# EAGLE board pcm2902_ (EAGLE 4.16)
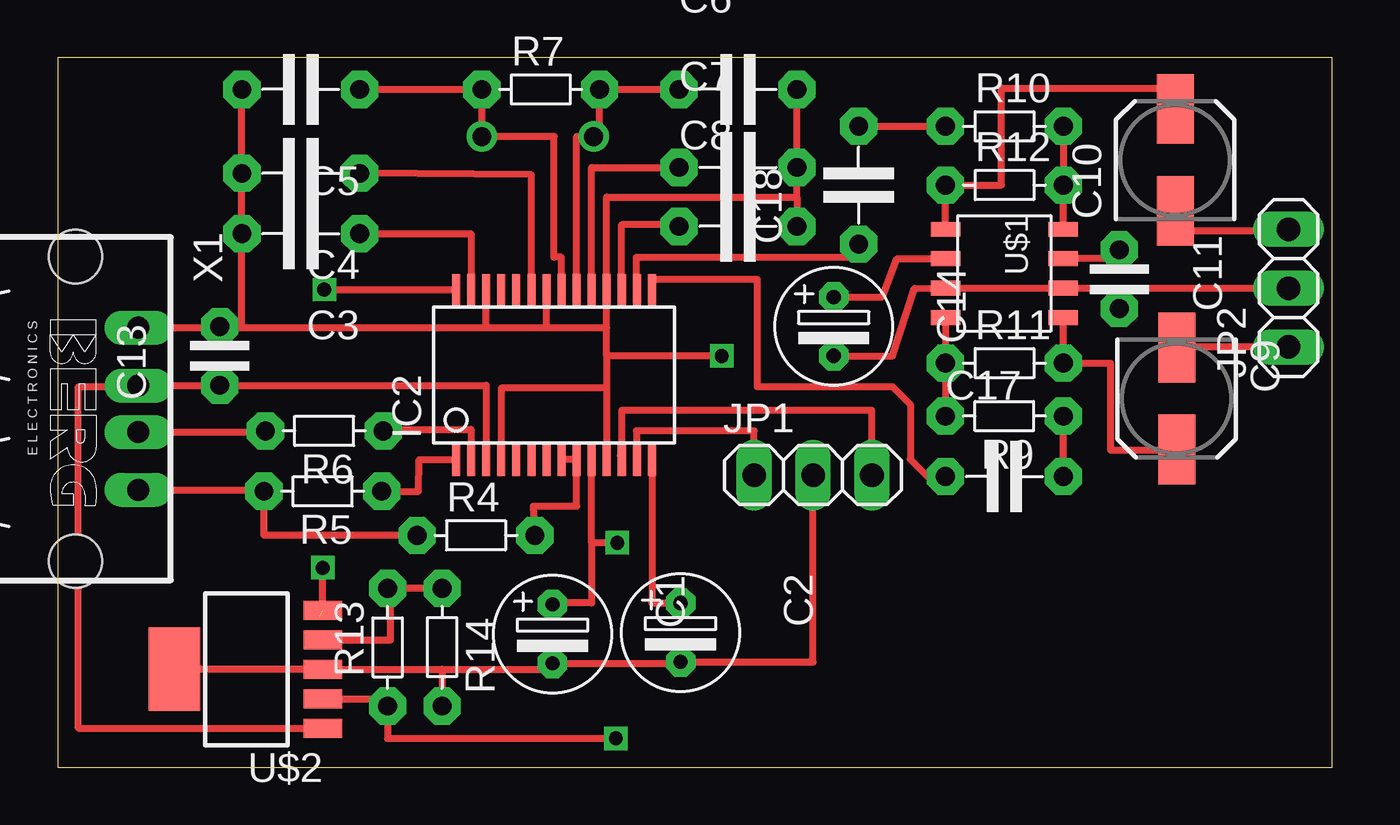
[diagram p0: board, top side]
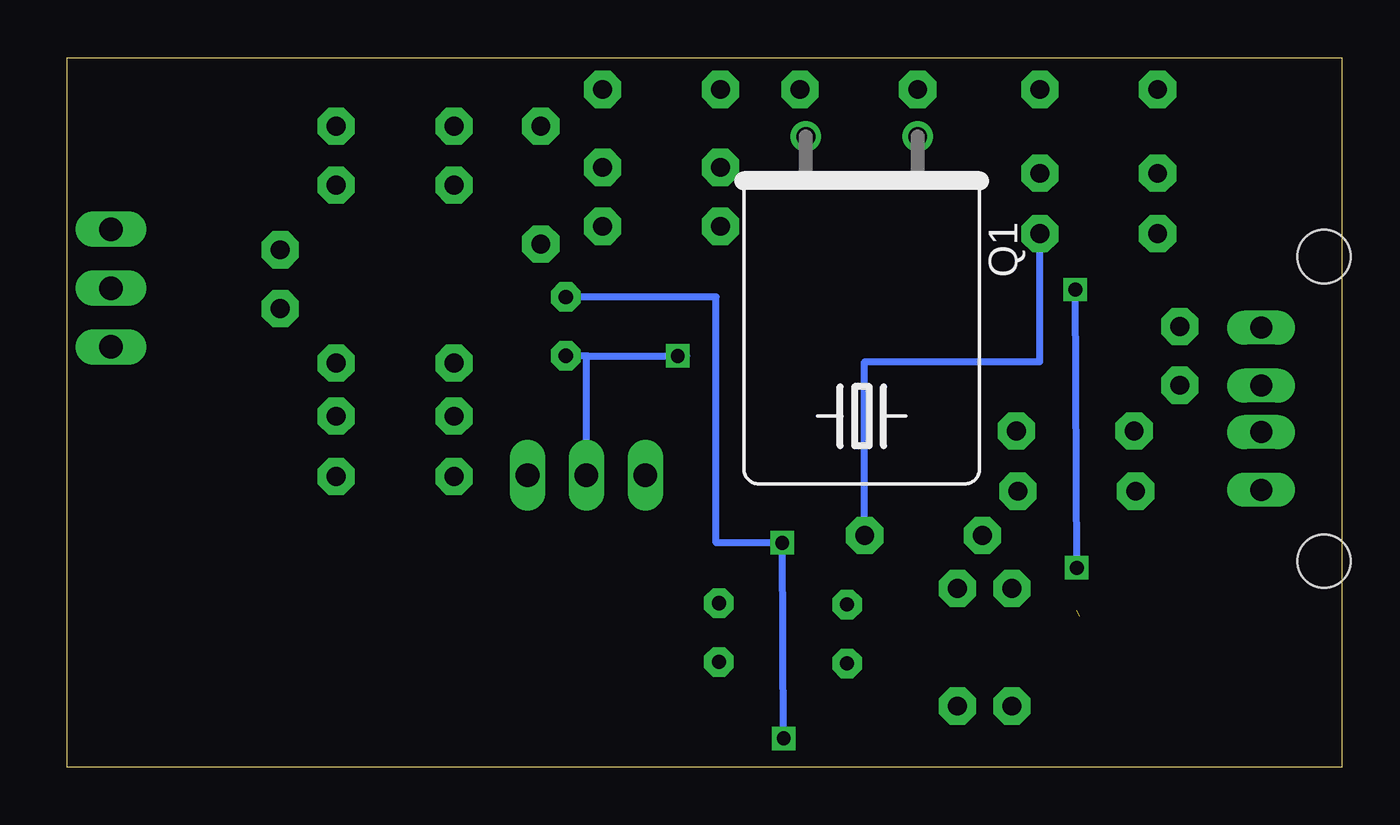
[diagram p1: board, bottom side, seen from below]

Size 54.97 x 30.59 mm. Coordinates in mm from the lower left corner, seen from the top.
Outline: 0,0 54.97,0 54.97,30.59 0,30.59 0,0
Copper layers (1*16): Top 0.035mm / dielectric 1.5mm / Bottom 0.035mm
Design rules "default": minimum track width 10mil, minimum drill 24mil, track to track 8mil, track to pad 8mil, pad to pad 8mil, via to via 8mil, smd to smd 8mil, copper to edge 40mil, drill to drill 8mil, minimum pad ring 10mil, minimum via ring 8mil, stop-mask expansion 4mil, vias tented up to drill 0mil, thermal gap 10mil

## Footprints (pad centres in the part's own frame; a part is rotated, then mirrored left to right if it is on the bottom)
ES-2,5L = drill 0.61 pad 1.27 octagon: 1 0,0; 2 2.54,0
C-5 = drill 0.813 pad 1.6 octagon: 1 -2.54,0; 2 2.54,0
SANYO-OSCON_SMD_B6 = smd 3 x 1.6: + 2.2,0; - -2.2,0
C-2,5 = drill 0.813 pad 1.6 octagon: 1 -1.27,0; 2 1.27,0
SSOP28DB = smd 0.348 x 1.397: 1 -4.225,-3.656; 2 -3.575,-3.656; 3 -2.925,-3.656; 4 -2.275,-3.656; 5 -1.625,-3.656; 6 -0.975,-3.656; 7 -0.325,-3.656; 8 0.325,-3.656; 9 0.975,-3.656; 10 1.625,-3.656; 11 2.275,-3.656; 12 2.925,-3.656; 13 3.575,-3.656; 14 4.225,-3.656; 15 4.225,3.656; 16 3.575,3.656; 17 2.925,3.656; 18 2.275,3.656; 19 1.625,3.656; 20 0.975,3.656; 21 0.325,3.656; 22 -0.325,3.656; 23 -0.975,3.656; 24 -1.625,3.656; 25 -2.275,3.656; 26 -2.925,3.656; 27 -3.575,3.656; 28 -4.225,3.656
1X03 = drill 1.016 long: 1 -2.54,0; 2 0,0; 3 2.54,0
HC49U-H = drill 0.813 round: 1 -2.413,-5.08; 2 2.413,-5.08
R-5 = drill 0.813 pad 1.6 octagon: 1 -2.54,0; 2 2.54,0
SOP8 = smd 0.635 x 1.27: 1 -1.905,-2.54; 2 -0.635,-2.54; 3 0.635,-2.54; 4 1.905,-2.54; 5 1.905,2.54; 6 0.635,2.54; 7 -0.635,2.54; 8 -1.905,2.54
SOT223-5 = smd 0.813 x 1.676: ADJ 1.27,-3.302; EN 2.54,-3.302; GND 0,-3.302; VIN -2.54,-3.302; VOUT -1.27,-3.302 | smd 3.6 x 2.2: TAB 0,3.099
PN87520 = drill 0.95 long: 1 -3.5,2.71; 2 -1,2.71; 3 1,2.71; 4 3.5,2.71 | hole 2.3: -6.57,0; 6.57,0

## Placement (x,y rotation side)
C1  10uF  [ES-2,5L]  21.33,7.01 270 top
C2  10uF  [ES-2,5L]  26.86,7.07 270 top
C3  1uF  [C-5]  10.47,23.01 180 top
C4  1uF  [C-5]  10.47,25.62 180 top
C5  33pF  [C-5]  10.47,29.24 180 top
C6  33pF  [C-5]  29.33,29.24 0 top
C7  1uF  [C-5]  29.33,25.87 0 top
C8  1uF  [C-5]  29.33,23.33 0 top
C9  100uF  [SANYO-OSCON_SMD_B6]  48.25,15.9 270 top
C10  100uF  [SANYO-OSCON_SMD_B6]  48.19,26.19 90 top
C11  2,2uF  [C-2,5]  45.78,21.04 270 top
C13  100nF  [C-2,5]  6.98,17.74 90 top
C14  10uF  [ES-2,5L]  33.46,20.28 270 top
C17  1uF  [C-5]  40.83,12.54 0 top
C18  1uF  [C-5]  34.54,25.11 90 top
IC2  PCM2902E  [SSOP28DB]  21.39,16.92 0 top
JP1  [1X03]  32.57,12.6 0 top
JP2  [1X03]  53.08,20.66 90 top
Q1  [HC49U-H]  20.7,22.12 180 bottom
R4  1,5k  [R-5]  18.03,10 0 top
R5  22  [R-5]  11.43,11.9 180 top
R6  22  [R-5]  11.49,14.5 180 top
R7  1M  [R-5]  20.82,29.24 0 top
R9  20k  [R-5]  40.83,15.14 180 top
R10  20k  [R-5]  40.83,27.65 0 top
R11  47k  [R-5]  40.83,17.42 0 top
R12  47k  [R-5]  40.83,25.11 0 top
R13  22k  [R-5]  14.22,5.17 90 top
R14  12k  [R-5]  16.57,5.17 270 top
U$1  TPA302  [SOP8]  40.83,21.3 90 top
U$2  REG102GA-A  [SOT223-5]  8.12,4.22 90 top
X1  [PN87520]  0.76,15.46 270 top

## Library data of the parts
C1-C8 C11 C13 C14 C17 C18 R4-R7 R9-R14 = discrete
C9 C10 = rcl
IC2 = texas
JP1 JP2 = pinhead
Q1 = crystal
U$1 = tpa302
U$2 = Reg102
X1 = con-berg

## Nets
DGND: C1.2 C2.2 C3.2 C4.2 C5.2 C6.2 C7.2 C8.2 C11.2 C13.2 C14.2 IC2.4 IC2.11 IC2.18 IC2.22 IC2.26 JP1.2 JP2.2 R14.2 U$1.2 U$1.7 U$2.GND U$2.TAB X1.1
N$1: C2.1 IC2.14
N$2: C1.1 C14.1 IC2.10 R13.1 U$1.6 U$2.VOUT
N$3: IC2.1 R5.1
N$4: R4.1 R5.2 X1.4
N$5: R6.2 X1.3
N$6: IC2.2 R6.1
N$8: C3.1 IC2.8 IC2.9 IC2.27 R4.2
N$14: C4.1 IC2.23
N$15: IC2.28 U$2.EN
N$16: IC2.12 JP1.3
N$17: IC2.13 JP1.1
N$18: C5.1 IC2.21 Q1.1 R7.1
N$19: C6.1 IC2.20 Q1.2 R7.2
N$20: C7.1 IC2.19
N$21: C8.1 IC2.17
N$24: C18.1 IC2.16
N$25: C17.1 IC2.15
N$26: R13.2 R14.1 U$2.ADJ
N$29: C11.1 U$1.3
N$30: C13.1 IC2.3 U$2.VIN X1.2
N$32: C17.2 R9.1
N$33: C18.2 R10.1
N$34: C10.+ R12.1 U$1.5
N$35: R10.2 R12.2 U$1.4
N$36: C9.+ R11.2 U$1.1
N$37: R9.2 R11.1 U$1.8
N$39: C9.- JP2.1
N$40: C10.- JP2.3

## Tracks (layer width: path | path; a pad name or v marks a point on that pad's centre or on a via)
DGND  (via drill 0.6)
  Top 0.305: 21.08,20.56 IC2.22 21.07,18.95 | 38.35,20.66 U$1.2 45.78,20.66 | 38.35,20.66 U$1.7 | 38.35,20.66 36.95,20.65 36,17.74 C14.2 | 23.67,20.54 IC2.18 23.67,24.6 31.87,24.6 | 23.67,17.74 23.67,18.95 | 23.67,17.74 23.67,16.35 | 23.67,16.35 IC2.11 | 23.67,18.95 23.67,20.54 | 23.67,20.54 23.68,20.54 | IC2.26 18.47,19.08 18.54,18.95 | 21.07,18.95 18.54,18.95 | 23.67,18.95 21.07,18.95 | IC2.4 19.12,16.35 23.67,16.35 | v28.63,17.74 23.67,17.74 | 31.87,24.6 C8.2 | 31.87,24.6 31.87,25.93 | 7.87,29.24 C5.2 C4.2 C3.2 7.93,18.95 | 31.87,25.93 C7.2 | 31.87,25.93 C6.2 | X1.1 3.66,18.95 6.98,18.95 | 6.98,18.95 C13.2 | 18.54,18.95 7.93,18.95 | 7.93,18.95 6.98,18.95 | 45.78,20.66 JP2.2 | 45.78,20.66 C11.2 | 16.57,4.22 U$2.GND 5.14,4.22 | 16.57,4.22 R14.2 | 16.57,4.22 21.33,4.22 C1.2 26.86,4.47 C2.2 | C2.2 26.79,4.53 | JP1.2 32.57,4.53 C2.2 | 5.14,4.22 U$2.TAB | 5.14,4.22 5.14,4.34
  Bottom 0.305: 32.51,17.74 v28.63,17.74 28.25,17.74 | 32.51,17.74 C14.2 | JP1.2 32.57,17.74 32.51,17.74
N$1
  Top 0.305: 26.98,7.07 C2.1 25.62,7.07 IC2.14
N$2  (via drill 0.6)
  Top 0.305: U$1.6 36.19,21.93 35.56,20.28 33.4,20.28 | C14.1 33.4,20.28 | 33.4,20.28 33.4,20.35 | U$2.VOUT 14.22,2.95 | 14.22,2.95 R13.1 | 21.33,7.07 21.27,7.07 | 21.33,7.07 C1.1 | 23.02,9.68 23.02,7.07 21.33,7.07 | 23.02,9.68 IC2.10 | 14.22,2.95 14.22,1.23 v24.06,1.23 | v24.13,9.68 23.02,9.68
  Bottom 0.305: 33.52,20.28 C14.1 26.98,20.28 26.98,9.68 v24.13,9.68 | v24.06,1.23 v24.13,9.68 | v24.13,9.68 24.06,9.68
N$3
  Top 0.305: R5.1 15.55,11.9 15.58,13.26 IC2.1
N$4
  Top 0.305: X1.4 8.89,11.96 R5.2 8.89,9.99 R4.1
N$5
  Top 0.305: X1.3 8.93,14.46 R6.2
N$6
  Top 0.305: R6.1 14.03,14.57 17.82,14.57 IC2.2
N$8  (via drill 0.6)
  Top 0.305: 21.72,13.24 21.71,13.23 | 21.72,13.24 IC2.8 | 21.72,13.24 21.74,13.26 IC2.9 22.37,11.27 20.51,11.27 R4.2 | 12.95,23.08 12.95,23.01 C3.1 17.82,23.01 IC2.27
  Bottom 0.305: C3.1 13.01,17.49 20.57,17.49 R4.2
  other vias: 13.01,23.01
N$14
  Top 0.305: IC2.23 20.42,25.55 C4.1
N$15  (via drill 0.6)  (1 unrouted)
  Top 0.305: IC2.28 17.17,20.6 v11.49,20.6 | U$2.EN v11.43,8.6
  Bottom 0.305: v11.43,8.6 v11.49,20.6
N$16
  Top 0.305: JP1.3 35.11,15.39 24.32,15.39 24.32,13.42 | 24.32,13.42 IC2.12 | 24.32,13.42 24.25,13.42
N$17
  Top 0.305: JP1.1 30.03,14.5 24.95,14.5 24.95,13.23 24.97,13.23 IC2.13
N$18
  Top 0.305: IC2.21 21.72,22 21.39,22 21.4,27.2 Q1.1 R7.1 C5.1
N$19
  Top 0.305: IC2.20 22.37,27.2 Q1.2 23.36,27.2 R7.2 C6.1
N$20
  Top 0.305: 26.86,25.93 C7.1 23.02,25.87 IC2.19
N$21
  Top 0.305: IC2.17 24.32,23.39 26.79,23.39 C8.1
N$24
  Top 0.305: IC2.16 24.95,20.57 24.95,22 34.54,22 C18.1
N$25
  Top 0.305: IC2.15 25.62,21.04 30.16,21.04 30.16,16.41 36,16.41 36.76,15.64 36.76,13.28 37.5,12.53 C17.1
N$26
  Top 0.305: U$2.ADJ 14.35,5.49 14.35,6.82 R13.2 R14.1
N$29
  Top 0.305: C11.1 45.78,21.93 U$1.3
N$30
  Top 0.305: 18.47,16.47 IC2.3 | 11.49,1.68 U$2.VIN 0.88,1.68 0.88,16.41 3.49,16.41 3.49,16.46 X1.2 3.53,16.47 C13.1 18.47,16.47 | 18.47,16.47
N$32
  Top 0.305: C17.2 R9.1
N$33
  Top 0.305: C18.2 R10.1
N$34
  Top 0.305: U$1.5 R12.1 40.7,25.11 40.7,29.3 47.62,29.3 47.62,29.28 C10.+
N$35
  Top 0.305: U$1.4 43.37,24.98 | 43.37,24.98 R12.2 | R10.2 43.37,24.98
N$36
  Top 0.305: U$1.1 R11.2 45.4,17.42 45.4,13.68 48.25,13.68 C9.+
N$37
  Top 0.305: U$1.8 R11.1 R9.2 38.29,15.07
N$39
  Top 0.305: C9.- 48.25,18.12 JP2.1
N$40
  Top 0.305: JP2.3 52.7,23.14 48.19,23.14 C10.-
